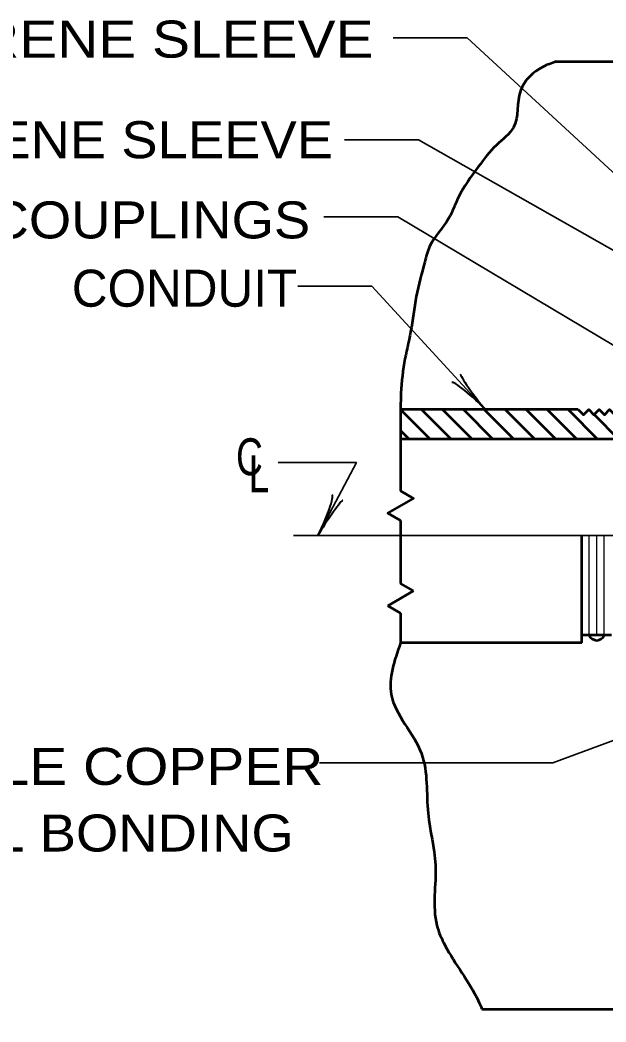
# Model space of a CAD drawing. Extents: x -50 to 806, y -9 to 535.
# Drawn here: x 104.4 to 151.9, y 352.2 to 433.4 of the extents above; entities that cross this region are included whole.
import ezdxf

# ---------------------------------------------------------------- set-up
doc = ezdxf.new("R2010")
doc.units = 0
doc.header["$LTSCALE"] = 1.2
doc.layers.add('1', color=7, linetype='Continuous', lineweight=35)

msp = doc.modelspace()

# ---------------------------------------------------------------- linework, layer by layer
at = {"layer": '1'}
for p, q in [((134.624, 431.971), (140.624, 431.971)), ((170.021, 404.851), (140.624, 431.971)), ((130.673, 423.714), (136.673, 423.714)), ((162.821, 408.881), (136.673, 423.714)), ((129.005, 417.478), (135.005, 417.478)), ((156.194, 404.851), (135.005, 417.478)), ((126.898, 411.857), (132.898, 411.857)), ((142.089, 401.851), (132.898, 411.857)), ((147.571, 373.228), (156.418, 376.486)), ((147.571, 373.228), (128.65, 373.228))]:
    msp.add_line(p, q, dxfattribs=at)
at = {"layer": '1', "lineweight": 53}
for p, q in [((149.621, 401.851), (135.221, 401.851)), ((135.221, 401.851), (135.221, 395.251)), ((135.221, 401.851), (137.621, 399.451)), ((136.918, 401.851), (139.318, 399.451)), ((138.615, 401.851), (141.015, 399.451)), ((140.312, 401.851), (142.712, 399.451)), ((142.009, 401.851), (144.409, 399.451)), ((143.706, 401.851), (146.106, 399.451)), ((145.403, 401.851), (147.803, 399.451)), ((147.1, 401.851), (149.5, 399.451)), ((148.798, 401.851), (151.198, 399.451)), ((150.906, 401.439), (152.894, 399.451)), ((135.221, 400.154), (135.924, 399.451)), ((158.956, 399.451), (135.221, 399.451)), ((135.221, 392.851), (135.221, 387.751)), ((149.921, 382.951), (149.921, 391.651)), ((136.26, 387.151), (135.221, 387.751)), ((134.182, 385.951), (136.26, 387.151)), ((135.221, 385.351), (134.182, 385.951)), ((135.221, 385.351), (135.221, 382.951)), ((152.321, 383.551), (149.921, 383.551)), ((149.921, 382.951), (135.221, 382.951))]:
    msp.add_line(p, q, dxfattribs=at)
at = {"layer": '1', "lineweight": 25}
for p, q in [((150.521, 383.551), (150.521, 391.651)), ((151.121, 383.551), (151.121, 391.651)), ((151.721, 383.551), (151.721, 391.651))]:
    msp.add_line(p, q, dxfattribs=at)
at = {"layer": '1', "lineweight": 53}
for points in [[(147.821, 430.051), (181.421, 430.051), (182.021, 429.012), (183.221, 431.09), (183.821, 430.051)], [(149.621, 401.851), (150.045, 401.427), (150.47, 401.851), (150.894, 401.427), (151.318, 401.851), (151.743, 401.427), (152.167, 401.851), (152.591, 401.427), (153.016, 401.851), (153.44, 401.427), (153.864, 401.851), (154.288, 401.427), (154.713, 401.851), (155.137, 401.427), (155.561, 401.851), (155.986, 401.427), (156.41, 401.851), (156.834, 401.427), (157.258, 401.851), (157.683, 401.427), (158.107, 401.851), (158.531, 401.427), (158.956, 401.851)], [(135.221, 392.851), (134.182, 393.451), (136.26, 394.651), (135.221, 395.251)], [(141.821, 353.251), (165.821, 353.251), (166.421, 352.212), (167.621, 354.29), (168.221, 353.251)]]:
    msp.add_lwpolyline(points, dxfattribs=at)
at = {"layer": '1'}
for points in [[(128.525, 391.651), (131.647, 397.55), (125.311, 397.55)], [(126.556, 391.651), (152.321, 391.651), (158.956, 391.651)]]:
    msp.add_lwpolyline(points, dxfattribs=at)
at = {"layer": '1', "lineweight": 53}
msp.add_arc((151.121, 383.791), 0.646, 201.77847, 338.22153, dxfattribs=at)
at = {"layer": '1', "lineweight": 40}
for centre, major_axis, ratio, start_param, end_param in [((141.367, 403.013), (-1.271, 1.695), 0.07063, 6.282307, 8.559703), ((140.959, 402.591), (1.588, -1.451), 0.122415, 0.896353, 3.141593), ((128.844, 392.963), (-0.837, -1.982), 0.122415, 0.896353, 3.141593), ((128.844, 392.963), (-0.837, -1.982), 0.122415, 0.896353, 3.141593), ((129.378, 392.721), (-1.172, -1.764), 0.07063, 3.140715, 5.41811), ((129.378, 392.721), (-1.172, -1.764), 0.07063, 3.140715, 5.41811)]:
    msp.add_ellipse(centre, major_axis=major_axis, ratio=ratio, start_param=start_param, end_param=end_param, dxfattribs=at)
at = {"layer": '1', "lineweight": 53}
for points in [[(147.821, 430.051), (146.773, 429.631), (144.946, 427.688), (144.374, 424.718), (143.004, 423.289), (141.519, 421.518), (139.92, 419.062), (139.12, 417.348), (137.578, 415.063), (137.179, 413.806), (136.493, 411.007), (136.036, 408.15), (135.522, 405.637), (135.237, 402.837), (135.221, 401.851)], [(135.221, 382.951), (134.461, 378.747), (136.911, 373.966), (137.448, 369.125), (138.046, 364.942), (138.165, 360.041), (138.822, 358.427), (141.511, 353.945), (141.821, 353.251)]]:
    msp.add_spline(points, degree=3, dxfattribs=at)

# ---------------------------------------------------------------- texts
at = {"layer": '1'}
for s, width, p in [('TEETH TO GRIP NEOPRENE SLEEVE', 1.15, (51.251, 430.379)), ('MOLDED NEOPRENE SLEEVE', 1.1, (66.487, 422.223)), ('SILICON BRONZE COUPLINGS', 1.1, (63.41, 415.723)), ('C', 0.75, (121.887, 396.523)), ('L', 0.75, (122.914, 395.152)), ('TINNED FLEXIBLE COPPER', 1.15, (68.206, 371.427)), ('BRAID INTERNAL BONDING', 1.1, (68.206, 366.027))]:
    msp.add_text(s, height=3, dxfattribs=dict(at, width=width)).set_placement(p)
msp.add_text('CONDUIT', height=3, dxfattribs=at).set_placement((108.576, 410.188))

doc.saveas('drawing.dxf')
